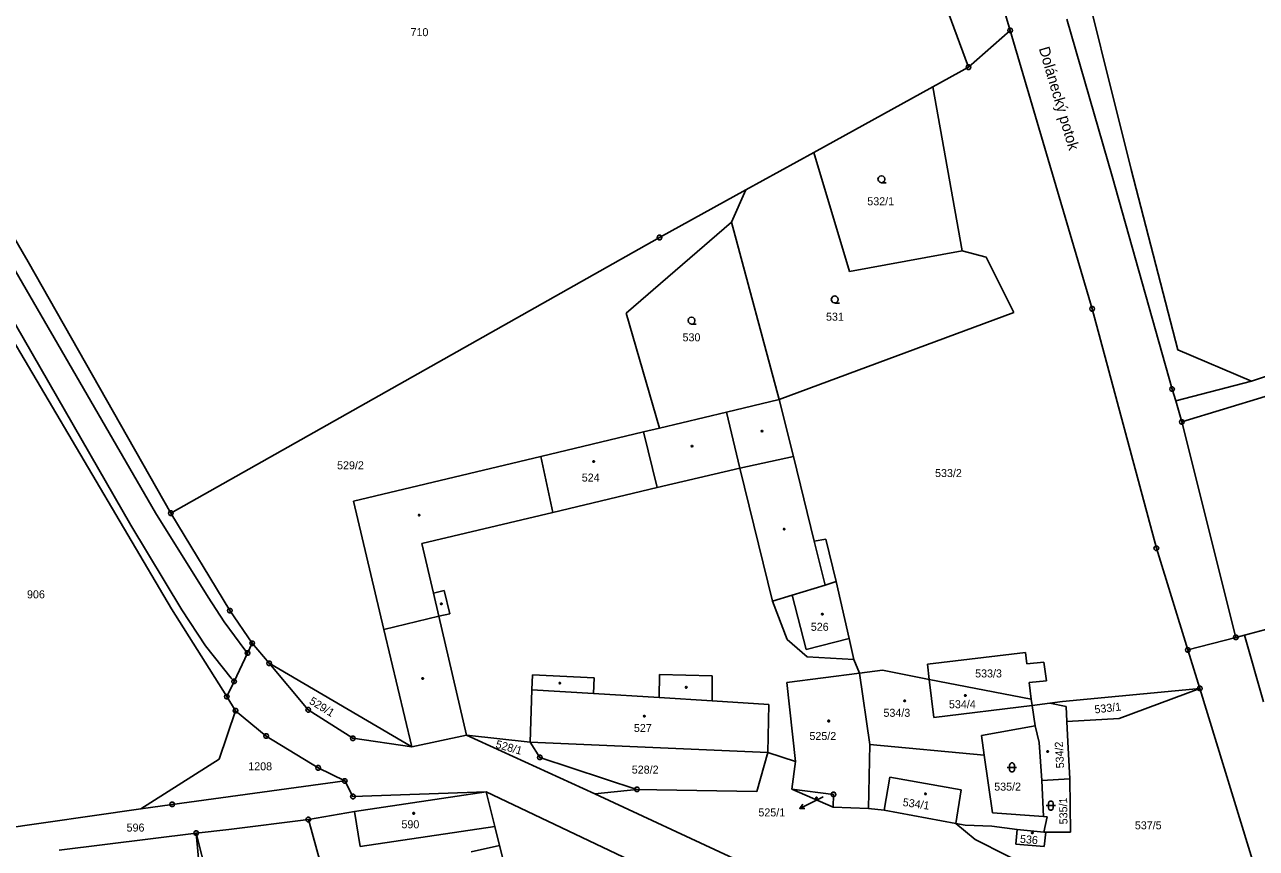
# Model space of a CAD drawing. Extents: x -812394 to -807601, y -1013098 to -1009266.
# Drawn here: x -809265.1 to -809003.5, y -1011662.3 to -1011487.4 of the extents above; entities that cross this region are included whole.
import ezdxf

# ---------------------------------------------------------------- set-up
doc = ezdxf.new("R2010")
doc.units = 0
for name, color, linetype in [('KN_HRANICE', 7, 'Continuous'), ('KN_KULTURY', 7, 'Continuous'), ('KN_MEZNIKY', 7, 'Continuous'), ('KN_PARCELY', 7, 'Continuous'), ('KN_SLUCKY', 7, 'Continuous')]:
    doc.layers.add(name, color=color, linetype=linetype)

# ---------------------------------------------------------------- blocks, each defined once
blk = doc.blocks.new('304')
blk.add_lwpolyline([(0, 0), (-0.38, 0.1), (-0.65, 0.37), (-0.75, 0.74), (-0.65, 1.11), (-0.38, 1.38), (-0.01, 1.48), (0.36, 1.38), (0.63, 1.11), (0.73, 0.73), (0.63, 0.35), (0.36, 0.08), (-0.02, -0.02), (0.98, -0.02)])
blk = doc.blocks.new('316')
for points in [[(-1, 1), (0.27, 1), (1, 1)], [(-0.5, 1.5), (-0.4, 1.79), (-0.15, 1.97), (0.16, 1.97), (0.41, 1.79), (0.51, 1.5), (0.51, 0.5), (0.41, 0.21), (0.16, 0.03), (-0.15, 0.03), (-0.4, 0.21), (-0.5, 0.5), (-0.5, 1.5)]]:
    blk.add_lwpolyline(points)
blk = doc.blocks.new('NAHRADNI_SYMBOL')
blk.add_lwpolyline([(0.09, 0.15), (0.18, 0), (0.09, -0.15), (-0.09, -0.15), (-0.18, 0), (-0.09, 0.15), (0.09, 0.15)])
blk = doc.blocks.new('10292')
blk.add_line((0, 3), (0, 0))
blk.add_lwpolyline([(-0.5, 2), (0, 3), (0.5, 2)])
blk = doc.blocks.new('402')
blk.add_lwpolyline([(0.09, 0.15), (0.18, 0), (0.09, -0.15), (-0.09, -0.15), (-0.18, 0), (-0.09, 0.15), (0.09, 0.15)])
blk = doc.blocks.new('105')
blk.add_line((-0.12, 0), (0.12, 0))
blk.add_lwpolyline([(0.15, 0.48), (0.4, 0.3), (0.5, 0.01), (0.4, -0.28), (0.15, -0.46), (-0.16, -0.46), (-0.41, -0.28), (-0.51, 0.01), (-0.41, 0.3), (-0.16, 0.48), (0.15, 0.48)])

msp = doc.modelspace()

# ---------------------------------------------------------------- linework, layer by layer
at = {"layer": 'KN_HRANICE'}
for p, q in [((-809064.62, -1011496.45), (-809087.91, -1011433.54)), ((-809062.99, -1011464.38), (-809055.78, -1011488.65)), ((-809264.38, -1011537.81), (-809303.36, -1011470.45)), ((-809043.77, -1011486.23), (-809034.16, -1011519.56)), ((-809055.78, -1011488.65), (-809064.62, -1011496.45)), ((-809038.36, -1011547.76), (-809055.78, -1011488.65)), ((-809072.23, -1011500.64), (-809064.62, -1011496.45)), ((-809097.48, -1011514.55), (-809072.23, -1011500.64)), ((-809065.99, -1011535.45), (-809072.23, -1011500.64)), ((-809292.61, -1011512.1), (-809233.88, -1011611.48)), ((-809111.92, -1011522.51), (-809097.48, -1011514.55)), ((-809089.91, -1011539.85), (-809097.48, -1011514.55)), ((-809034.16, -1011519.56), (-809021.4, -1011564.8)), ((-809130.26, -1011532.62), (-809111.92, -1011522.51)), ((-809114.97, -1011529.38), (-809111.92, -1011522.51)), ((-809137.33, -1011548.69), (-809114.97, -1011529.38)), ((-809114.97, -1011529.38), (-809104.83, -1011566.99)), ((-809130.26, -1011532.62), (-809234.03, -1011591.15)), ((-809065.99, -1011535.45), (-809089.91, -1011539.85)), ((-809060.91, -1011536.79), (-809065.99, -1011535.45)), ((-809055.04, -1011548.54), (-809060.91, -1011536.79)), ((-809234.03, -1011591.15), (-809264.38, -1011537.81)), ((-809130.29, -1011573.09), (-809137.33, -1011548.69)), ((-809104.83, -1011566.99), (-809055.04, -1011548.54)), ((-809024.74, -1011598.61), (-809038.36, -1011547.76)), ((-809004.54, -1011563.13), (-808974.75, -1011553.11)), ((-809004.54, -1011563.13), (-809020.63, -1011567.3)), ((-809021.4, -1011564.8), (-809020.63, -1011567.3)), ((-809116.05, -1011569.68), (-809104.83, -1011566.99)), ((-809104.83, -1011566.99), (-809101.83, -1011579.14)), ((-809019.32, -1011571.78), (-809001.64, -1011566.41)), ((-809130.29, -1011573.09), (-809116.05, -1011569.68)), ((-809133.63, -1011573.89), (-809130.29, -1011573.09)), ((-809007.85, -1011617.52), (-809019.32, -1011571.78)), ((-809155.46, -1011579.11), (-809133.63, -1011573.89)), ((-809195.25, -1011588.63), (-809155.46, -1011579.11)), ((-809101.83, -1011579.14), (-809097.4, -1011597.08)), ((-809195.25, -1011588.63), (-809188.78, -1011615.82)), ((-809234.03, -1011591.15), (-809221.52, -1011611.85)), ((-809097.4, -1011597.08), (-809094.96, -1011596.66)), ((-809097.4, -1011597.08), (-809095.09, -1011606.41)), ((-809092.74, -1011605.67), (-809094.96, -1011596.66)), ((-809018.04, -1011620.2), (-809024.74, -1011598.61)), ((-809095.09, -1011606.41), (-809102.07, -1011608.57)), ((-809092.74, -1011605.67), (-809090.01, -1011617.74)), ((-809102.07, -1011608.57), (-809106.29, -1011609.87)), ((-809103.15, -1011617.95), (-809106.29, -1011609.87)), ((-809006.01, -1011617.04), (-808975.11, -1011608.93)), ((-809233.88, -1011611.48), (-809222.17, -1011630.1)), ((-809221.52, -1011611.85), (-809216.75, -1011618.78)), ((-809188.78, -1011615.82), (-809182.84, -1011640.8)), ((-809098.87, -1011621.67), (-809103.15, -1011617.95)), ((-809090.01, -1011617.74), (-809089, -1011622.23)), ((-809007.85, -1011617.52), (-809018.04, -1011620.2)), ((-809006.01, -1011617.04), (-809007.85, -1011617.52)), ((-809002.01, -1011631.2), (-809006.01, -1011617.04)), ((-809216.75, -1011618.78), (-809217.74, -1011620.85)), ((-809216.75, -1011618.78), (-809213.17, -1011623.03)), ((-809073.36, -1011623.22), (-809052.52, -1011620.7)), ((-809052.52, -1011620.7), (-809052.22, -1011623.16)), ((-809018.04, -1011620.2), (-809015.5, -1011628.37)), ((-809217.74, -1011620.85), (-809220.61, -1011626.88)), ((-809213.17, -1011623.03), (-809204.85, -1011632.91)), ((-809182.84, -1011640.8), (-809213.17, -1011623.03)), ((-809089, -1011622.23), (-809098.87, -1011621.67)), ((-809087.79, -1011625.14), (-809089, -1011622.23)), ((-809072.97, -1011626.45), (-809073.36, -1011623.22)), ((-809052.22, -1011623.16), (-809048.61, -1011622.78)), ((-809048.61, -1011622.78), (-809048.07, -1011626.76)), ((-809157.25, -1011625.5), (-809157.35, -1011628.65)), ((-809157.25, -1011625.5), (-809144.15, -1011626.08)), ((-809130.23, -1011625.41), (-809130.3, -1011630.32)), ((-809119.05, -1011625.68), (-809130.23, -1011625.41)), ((-809119.05, -1011631.02), (-809119.05, -1011625.68)), ((-809103.23, -1011627.09), (-809087.79, -1011625.14)), ((-809087.79, -1011625.14), (-809082.89, -1011624.52)), ((-809087.79, -1011625.14), (-809085.58, -1011640.3)), ((-809072.97, -1011626.45), (-809082.89, -1011624.52)), ((-809220.61, -1011626.88), (-809222.17, -1011630.1)), ((-809144.15, -1011626.08), (-809144.3, -1011629.46)), ((-809101.39, -1011643.91), (-809103.23, -1011627.09)), ((-809051.31, -1011630.65), (-809072.97, -1011626.45)), ((-809071.99, -1011634.54), (-809072.97, -1011626.45)), ((-809048.07, -1011626.76), (-809051.74, -1011627.11)), ((-809051.74, -1011627.11), (-809051.31, -1011630.65)), ((-809044.66, -1011631.11), (-809015.5, -1011628.37)), ((-809015.5, -1011628.37), (-809032.61, -1011634.74)), ((-809015.5, -1011628.37), (-808997.45, -1011687.11)), ((-809222.17, -1011630.1), (-809220.29, -1011633.09)), ((-809157.35, -1011628.65), (-809157.72, -1011639.81)), ((-809130.3, -1011630.32), (-809144.3, -1011629.46)), ((-809107.02, -1011631.76), (-809119.05, -1011631.02)), ((-809051.31, -1011630.65), (-809051.15, -1011632.01)), ((-809047.34, -1011631.48), (-809044.66, -1011631.11)), ((-809220.29, -1011633.09), (-809223.81, -1011643.41)), ((-809220.29, -1011633.09), (-809213.78, -1011638.47)), ((-809204.85, -1011632.91), (-809195.39, -1011638.95)), ((-809107.24, -1011641.99), (-809107.02, -1011631.76)), ((-809051.15, -1011632.01), (-809071.99, -1011634.54)), ((-809051.15, -1011632.01), (-809047.34, -1011631.48)), ((-809050.46, -1011636.33), (-809051.15, -1011632.01)), ((-809043.93, -1011632.19), (-809047.34, -1011631.48)), ((-809043.78, -1011635.36), (-809043.93, -1011632.19)), ((-809061.88, -1011638.33), (-809050.46, -1011636.33)), ((-809049.65, -1011639.88), (-809050.46, -1011636.33)), ((-809032.61, -1011634.74), (-809043.78, -1011635.36)), ((-809043.57, -1011639.69), (-809043.78, -1011635.36)), ((-809213.78, -1011638.47), (-809202.74, -1011645.23)), ((-809195.39, -1011638.95), (-809182.84, -1011640.8)), ((-809182.84, -1011640.8), (-809171.23, -1011638.28)), ((-809171.23, -1011638.28), (-809144.03, -1011650.78)), ((-809171.23, -1011638.28), (-809157.72, -1011639.81)), ((-809061.33, -1011642.55), (-809061.88, -1011638.33)), ((-809157.72, -1011639.81), (-809107.24, -1011641.99)), ((-809157.72, -1011639.81), (-809155.66, -1011643.03)), ((-809085.58, -1011640.3), (-809085.85, -1011653.87)), ((-809085.58, -1011640.3), (-809061.33, -1011642.55)), ((-809049.03, -1011647.94), (-809049.65, -1011639.88)), ((-809043.57, -1011639.69), (-809043.09, -1011647.59)), ((-809223.81, -1011643.41), (-809240.39, -1011653.93)), ((-809155.66, -1011643.03), (-809135.05, -1011649.8)), ((-809109.56, -1011650.26), (-809107.24, -1011641.99)), ((-809107.24, -1011641.99), (-809101.39, -1011643.91)), ((-809102.17, -1011649.74), (-809101.39, -1011643.91)), ((-809061.33, -1011642.55), (-809059.57, -1011654.76)), ((-809202.74, -1011645.23), (-809197.11, -1011648.02)), ((-809197.11, -1011648.02), (-809233.77, -1011652.99)), ((-809195.36, -1011651.32), (-809197.11, -1011648.02)), ((-809043.09, -1011647.59), (-809049.03, -1011647.94)), ((-809048.69, -1011655.54), (-809049.03, -1011647.94)), ((-809042.98, -1011658.92), (-809043.09, -1011647.59)), ((-809167.11, -1011650.32), (-809195.36, -1011651.32)), ((-809167.11, -1011650.32), (-809195.04, -1011654.47)), ((-809165.24, -1011657.69), (-809167.11, -1011650.32)), ((-809118.81, -1011673.24), (-809167.11, -1011650.32)), ((-809135.05, -1011649.8), (-809144.03, -1011650.78)), ((-809144.03, -1011650.78), (-809114.47, -1011664.51)), ((-809135.05, -1011649.8), (-809109.56, -1011650.26)), ((-809093.35, -1011653.56), (-809102.17, -1011649.74)), ((-809102.17, -1011649.74), (-809093.31, -1011650.88)), ((-809093.31, -1011650.88), (-809093.35, -1011653.56)), ((-809240.39, -1011653.93), (-809284.79, -1011660.24)), ((-809233.77, -1011652.99), (-809240.39, -1011653.93)), ((-809195.04, -1011654.47), (-809204.84, -1011656.21)), ((-809085.85, -1011653.87), (-809093.35, -1011653.56)), ((-809085.85, -1011653.87), (-809082.52, -1011654.22)), ((-809082.52, -1011654.22), (-809067.32, -1011657.02)), ((-809059.57, -1011654.76), (-809048.69, -1011655.54)), ((-809221.7, -1011658.29), (-809204.84, -1011656.21)), ((-809204.84, -1011656.21), (-809195.9, -1011688.5)), ((-809067.32, -1011657.02), (-809063.24, -1011660.46)), ((-809067.32, -1011657.02), (-809065.36, -1011657.38)), ((-809065.36, -1011657.38), (-809059.71, -1011657.61)), ((-809048.69, -1011655.54), (-809047.95, -1011655.61)), ((-809047.95, -1011655.61), (-809048.64, -1011658.88)), ((-809257.74, -1011662.73), (-809228.66, -1011659.08)), ((-809228.66, -1011659.08), (-809221.7, -1011658.29)), ((-809218.66, -1011698.01), (-809228.66, -1011659.08)), ((-809228.66, -1011659.08), (-809224.05, -1011707.64)), ((-809165.24, -1011657.69), (-809164.26, -1011661.71)), ((-809054.31, -1011658.32), (-809059.71, -1011657.61)), ((-809054.58, -1011661.43), (-809054.31, -1011658.32)), ((-809054.31, -1011658.32), (-809048.64, -1011658.88)), ((-809048.64, -1011658.88), (-809048.2, -1011658.92)), ((-809048.2, -1011658.92), (-809048.58, -1011661.92)), ((-809048.2, -1011658.92), (-809042.98, -1011658.92)), ((-809164.26, -1011661.71), (-809170.27, -1011663.04)), ((-809164.26, -1011661.71), (-809163.49, -1011664.76)), ((-809063.24, -1011660.46), (-809049.78, -1011667.23)), ((-809048.58, -1011661.92), (-809054.58, -1011661.43))]:
    msp.add_line(p, q, dxfattribs=at)
for points in [[(-809004.54, -1011563.13), (-809020.2, -1011556.5), (-809030.08, -1011518.19), (-809042.88, -1011466.74), (-809050.93, -1011432.87), (-809048.08, -1011401.48), (-809039.69, -1011388.93)], [(-809019.32, -1011571.78), (-809020.33, -1011568.3), (-809020.63, -1011567.3)]]:
    msp.add_lwpolyline(points, dxfattribs=at)
at = {"layer": 'KN_PARCELY'}
msp.add_line((-809095.51, -1011651.38), (-809097.8, -1011652.51), dxfattribs=at)
at = {"layer": 'KN_SLUCKY'}
for p, q in [((-809113.22, -1011581.56), (-809116.05, -1011569.68)), ((-809130.73, -1011585.72), (-809133.63, -1011573.89)), ((-809152.89, -1011590.98), (-809155.46, -1011579.11)), ((-809113.22, -1011581.56), (-809101.83, -1011579.14)), ((-809113.22, -1011581.56), (-809130.73, -1011585.72)), ((-809106.29, -1011609.87), (-809113.22, -1011581.56)), ((-809130.73, -1011585.72), (-809152.89, -1011590.98)), ((-809152.89, -1011590.98), (-809180.72, -1011597.59)), ((-809180.72, -1011597.59), (-809178.26, -1011608.13)), ((-809175.97, -1011607.59), (-809178.26, -1011608.13)), ((-809174.8, -1011612.5), (-809175.97, -1011607.59)), ((-809095.09, -1011606.41), (-809092.74, -1011605.67)), ((-809178.26, -1011608.13), (-809177.11, -1011613.05)), ((-809102.07, -1011608.57), (-809099.14, -1011620.13)), ((-809177.11, -1011613.05), (-809174.8, -1011612.5)), ((-809188.78, -1011615.82), (-809177.11, -1011613.05)), ((-809177.11, -1011613.05), (-809171.23, -1011638.28)), ((-809099.14, -1011620.13), (-809090.01, -1011617.74)), ((-809144.3, -1011629.46), (-809157.35, -1011628.65)), ((-809119.05, -1011631.02), (-809130.3, -1011630.32)), ((-809082.52, -1011654.22), (-809081.34, -1011647.24)), ((-809066.17, -1011649.93), (-809081.34, -1011647.24)), ((-809067.32, -1011657.02), (-809066.17, -1011649.93)), ((-809195.04, -1011654.47), (-809193.85, -1011661.92)), ((-809193.85, -1011661.92), (-809165.24, -1011657.69))]:
    msp.add_line(p, q, dxfattribs=at)
for points in [[(-809477.33, -1011213.73), (-809468.7, -1011231.04), (-809466.3, -1011235.58), (-809456.55, -1011254.86), (-809449.91, -1011267.96), (-809441.09, -1011285.07), (-809430.76, -1011302.18), (-809419.56, -1011317.87), (-809411.22, -1011327.4), (-809387.73, -1011352.07), (-809371.18, -1011371.12), (-809360.69, -1011383.93), (-809346.19, -1011404.36), (-809328.58, -1011433.04), (-809301.05, -1011480.59), (-809267.1, -1011539.59), (-809237.29, -1011591.06), (-809226.14, -1011608.98), (-809222.72, -1011614.25), (-809218.36, -1011620.14), (-809217.74, -1011620.85)], [(-809220.61, -1011626.88), (-809221.24, -1011626.21), (-809226.68, -1011619.31), (-809231.69, -1011611.64), (-809242.51, -1011593.73), (-809272.24, -1011542.08), (-809306.38, -1011483.65), (-809333.58, -1011436.31), (-809351.23, -1011407.77), (-809365.24, -1011387.85), (-809375.71, -1011374.65), (-809392.11, -1011356.19), (-809415.64, -1011331.46), (-809424.36, -1011321.25), (-809437.25, -1011303.37), (-809444.34, -1011291.38), (-809452.42, -1011276.44), (-809461.77, -1011257.76), (-809482.94, -1011216.11)]]:
    msp.add_lwpolyline(points, dxfattribs=at)

# ---------------------------------------------------------------- block references
at = {"layer": 'KN_KULTURY'}
for name, p in [('304', (-809083.12, -1011520.97)), ('304', (-809093.04, -1011546.51)), ('304', (-809123.46, -1011550.99)), ('402', (-809108.5, -1011573.72)), ('402', (-809123.35, -1011576.94)), ('402', (-809144.23, -1011580.19)), ('402', (-809181.3, -1011591.55)), ('402', (-809103.79, -1011594.52)), ('402', (-809176.6, -1011610.42)), ('402', (-809095.68, -1011612.58)), ('402', (-809180.55, -1011626.23)), ('402', (-809151.42, -1011627.22)), ('402', (-809124.59, -1011628.14)), ('NAHRADNI_SYMBOL', (-809078.2, -1011631.01)), ('NAHRADNI_SYMBOL', (-809065.3, -1011629.86)), ('402', (-809133.48, -1011634.23)), ('NAHRADNI_SYMBOL', (-809094.32, -1011635.28)), ('NAHRADNI_SYMBOL', (-809047.84, -1011641.77)), ('316', (-809055.41, -1011646.14)), ('NAHRADNI_SYMBOL', (-809096.92, -1011651.62)), ('402', (-809073.78, -1011650.74)), ('402', (-809182.47, -1011654.89)), ('316', (-809047.16, -1011654.24)), ('402', (-809051.08, -1011659.05))]:
    msp.add_blockref(name, p, dxfattribs=at)
at = {"layer": 'KN_MEZNIKY'}
for p in [(-809055.78, -1011488.65), (-809064.62, -1011496.45), (-809130.26, -1011532.62), (-809038.36, -1011547.76), (-809021.4, -1011564.8), (-809019.32, -1011571.78), (-809234.03, -1011591.15), (-809024.74, -1011598.61), (-809221.52, -1011611.85), (-809007.85, -1011617.52), (-809217.74, -1011620.85), (-809216.75, -1011618.78), (-809018.04, -1011620.2), (-809213.17, -1011623.03), (-809220.61, -1011626.88), (-809015.5, -1011628.37), (-809222.17, -1011630.1), (-809220.29, -1011633.09), (-809204.85, -1011632.91), (-809213.78, -1011638.47), (-809195.39, -1011638.95), (-809155.66, -1011643.03), (-809202.74, -1011645.23), (-809197.11, -1011648.02), (-809135.05, -1011649.8), (-809195.36, -1011651.32), (-809093.31, -1011650.88), (-809233.77, -1011652.99), (-809204.84, -1011656.21), (-809228.66, -1011659.08)]:
    msp.add_blockref('105', p, dxfattribs=at)
at = {"layer": 'KN_PARCELY', "rotation": 116.31043199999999}
msp.add_blockref('10292', (-809097.8, -1011652.51), dxfattribs=at)

# ---------------------------------------------------------------- texts
at = {"layer": 'KN_PARCELY'}
for s, height, p in [('710', 1.7, (-809183.14, -1011489.86)), ('532/1', 1.7, (-809086.13, -1011525.77)), ('531', 1.7, (-809094.9, -1011550.28)), ('530', 1.7, (-809125.37, -1011554.66)), ('529/2', 1.7, (-809198.74, -1011581.83)), ('524', 1.7, (-809146.77, -1011584.44)), ('533/2', 1.7, (-809071.74, -1011583.48)), ('906', 1.7, (-809264.59, -1011609.23)), ('526', 1.7, (-809098.13, -1011616.13)), ('533/3', 1.7, (-809063.23, -1011626.03)), ('534/4', 1.7, (-809068.79, -1011632.57)), ('534/3', 1.7, (-809082.7, -1011634.39)), ('527', 1.7, (-809135.7, -1011637.61)), ('525/2', 1.7, (-809098.42, -1011639.32)), ('1208', 1.7, (-809217.6, -1011645.75)), ('528/2', 1.7, (-809136.15, -1011646.45)), ('535/2', 1.7, (-809059.18, -1011650.07)), ('525/1', 0.1, (-809095.74, -1011651.38)), ('525/1', 1.7, (-809109.26, -1011655.54)), ('596', 1.7, (-809243.44, -1011658.76)), ('590', 1.7, (-809185.07, -1011658.06)), ('537/5', 1.7, (-809029.31, -1011658.28))]:
    msp.add_text(s, height=height, dxfattribs=at).set_placement(p)
for s, height, rotation, p in [('Dolánecký potok', 2.3, 286.479, (-809049.73, -1011492.48)), ('529/1', 1.7, 328.362, (-809204.81, -1011631.49)), ('533/1', 1.7, 6.589, (-809037.79, -1011633.69)), ('528/1', 1.7, 344.29, (-809165.19, -1011640.93)), ('534/2', 1.7, 93.449, (-809044.31, -1011645.28)), ('534/1', 1.7, 351.739, (-809078.69, -1011653.31)), ('535/1', 1.7, 90.871, (-809043.61, -1011657.21)), ('536', 1.7, 354.89, (-809053.76, -1011661.12))]:
    msp.add_text(s, height=height, rotation=rotation, dxfattribs=at).set_placement(p)

doc.saveas('drawing.dxf')
